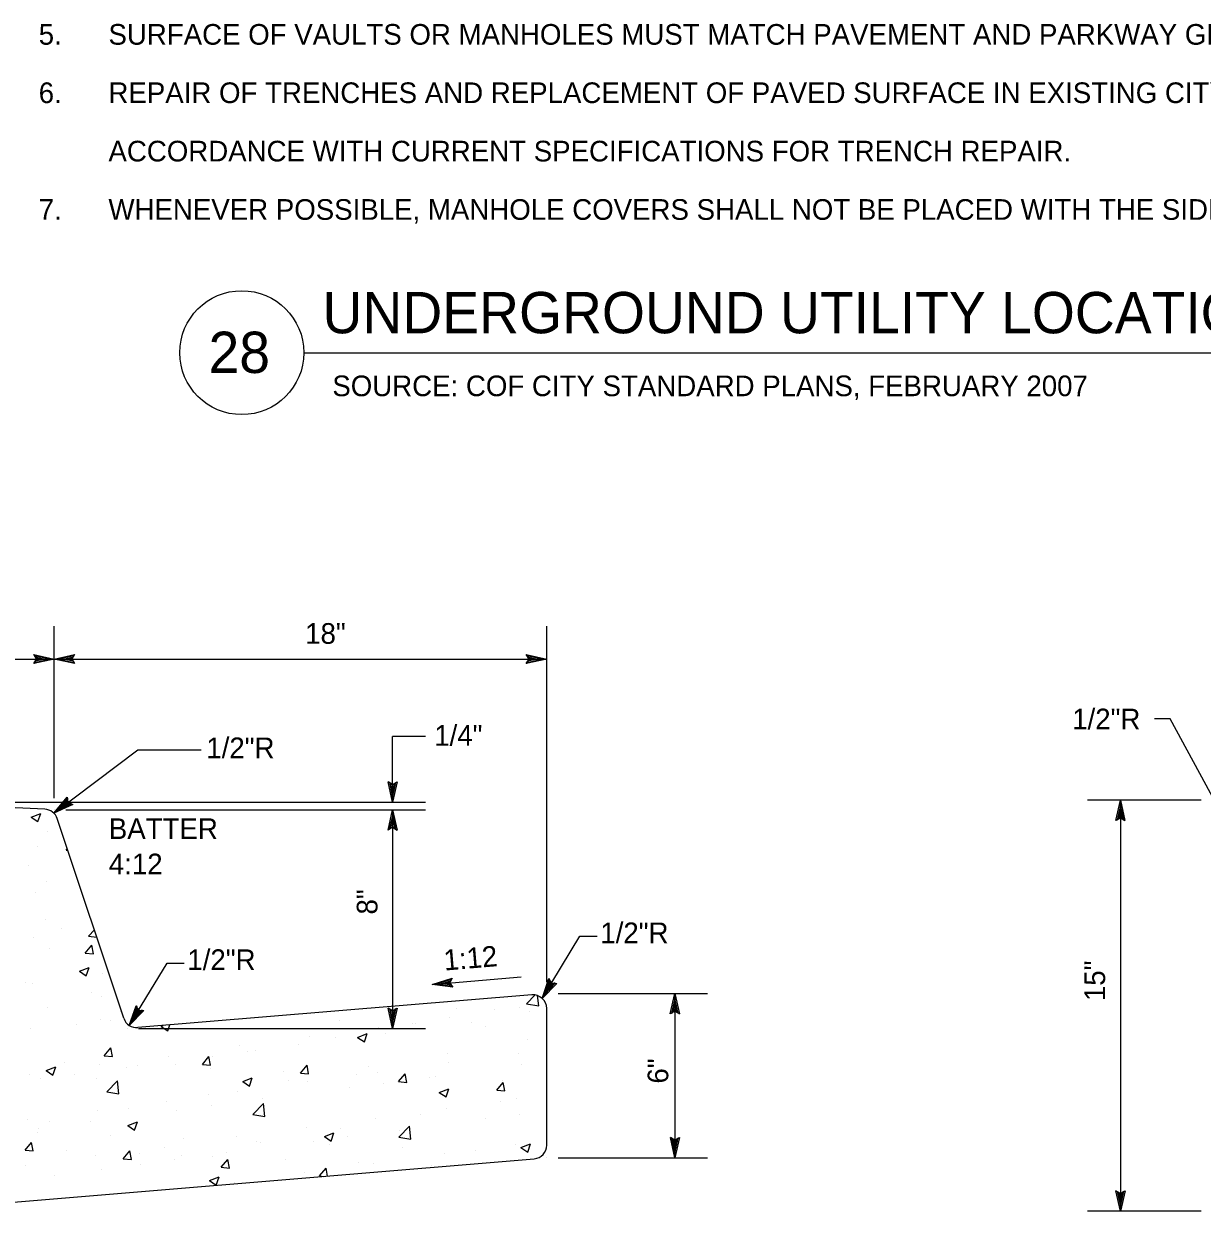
# Model space of a CAD drawing. Extents: x -119017 to -116080, y -104449 to -102845.
# Drawn here: x -118790 to -118447.9, y -103983.3 to -103638.4 of the extents above; entities that cross this region are included whole.
import ezdxf

# ---------------------------------------------------------------- set-up
doc = ezdxf.new("R2010")
doc.units = 0
for name, color, linetype in [('G-MARK', 7, 'Continuous'), ('G-TEXT', 7, 'Continuous'), ('Misc CnstDet(22)', 7, 'Continuous'), ('Nongeo Data(60)', 7, 'Continuous')]:
    doc.layers.add(name, color=color, linetype=linetype)

msp = doc.modelspace()

# ---------------------------------------------------------------- linework, layer by layer
at = {"layer": 'G-MARK'}
for p, q in [((-118781.19, -103863.3), (-118781.19, -103813.36)), ((-118638.22, -103916.71), (-118638.22, -103813.36)), ((-118828.88, -103822.9), (-118781.19, -103822.9)), ((-118781.19, -103822.9), (-118638.22, -103822.9)), ((-118682.94, -103864.49), (-118682.94, -103845.42)), ((-118673.4, -103845.42), (-118682.94, -103845.42)), ((-118448.18, -103863.93), (-118481.17, -103863.93)), ((-118471.63, -103863.93), (-118471.63, -103983.26)), ((-118825.53, -103864.49), (-118673.4, -103864.49)), ((-118777.85, -103866.65), (-118673.4, -103866.65)), ((-118682.94, -103866.65), (-118682.94, -103885.72)), ((-118682.94, -103876.19), (-118682.94, -103930.19)), ((-118671.49, -103917.37), (-118645.63, -103915.21)), ((-118634.87, -103920.06), (-118591.5, -103920.06)), ((-118601.01, -103920.06), (-118601.01, -103967.72)), ((-118756.68, -103930.19), (-118673.4, -103930.19)), ((-118634.87, -103967.72), (-118591.5, -103967.72)), ((-118448.18, -103983.26), (-118481.17, -103983.26))]:
    msp.add_line(p, q, dxfattribs=at)
for points in [[(-118443.61, -103865.21), (-118457.25, -103840.22), (-118461.72, -103840.22)], [(-118781.32, -103867.65), (-118756.89, -103849.23), (-118738.54, -103849.23)], [(-118639.5, -103921.44), (-118628.56, -103903.33), (-118623.59, -103903.33)]]:
    msp.add_lwpolyline(points, dxfattribs=at)
at = {"layer": 'G-TEXT'}
for points in [[(-118787.1, -103821.58), (-118781.19, -103822.9), (-118787.1, -103824.21), (-118786.89, -103823.86), (-118782.56, -103822.9), (-118786.89, -103821.93), (-118786.68, -103822.28), (-118783.91, -103822.9), (-118786.68, -103823.51), (-118786.47, -103823.16), (-118785.27, -103822.9), (-118786.47, -103822.63), (-118786.31, -103822.9), (-118787.1, -103824.21), (-118786.31, -103822.9)], [(-118775.29, -103824.22), (-118781.19, -103822.9), (-118775.29, -103821.59), (-118775.5, -103821.94), (-118779.82, -103822.9), (-118775.5, -103823.87), (-118775.7, -103823.52), (-118778.47, -103822.9), (-118775.71, -103822.29), (-118775.92, -103822.64), (-118777.11, -103822.9), (-118775.91, -103823.17), (-118776.07, -103822.9), (-118775.29, -103821.59), (-118776.07, -103822.9)], [(-118644.13, -103821.58), (-118638.22, -103822.9), (-118644.13, -103824.21), (-118643.92, -103823.86), (-118639.59, -103822.9), (-118643.92, -103821.93), (-118643.71, -103822.28), (-118640.94, -103822.9), (-118643.71, -103823.51), (-118643.5, -103823.16), (-118642.3, -103822.9), (-118643.5, -103822.63), (-118643.34, -103822.9), (-118644.13, -103824.21), (-118643.34, -103822.9)], [(-118681.62, -103858.59), (-118682.94, -103864.49), (-118684.25, -103858.59), (-118683.9, -103858.8), (-118682.94, -103863.12), (-118681.97, -103858.79), (-118682.32, -103859), (-118682.94, -103861.77), (-118683.55, -103859.01), (-118683.2, -103859.22), (-118682.93, -103860.41), (-118682.67, -103859.21), (-118682.94, -103859.37), (-118684.25, -103858.59), (-118682.94, -103859.37)], [(-118775.82, -103865.12), (-118781.32, -103867.65), (-118777.41, -103863.03), (-118777.37, -103863.43), (-118780.23, -103866.82), (-118776.2, -103864.97), (-118776.58, -103864.82), (-118779.15, -103866), (-118777.32, -103863.84), (-118777.28, -103864.24), (-118778.07, -103865.18), (-118776.95, -103864.66), (-118777.25, -103864.55), (-118777.41, -103863.03), (-118777.25, -103864.55)], [(-118472.95, -103869.83), (-118471.63, -103863.93), (-118470.32, -103869.83), (-118470.67, -103869.62), (-118471.63, -103865.3), (-118472.6, -103869.63), (-118472.25, -103869.42), (-118471.63, -103866.65), (-118471.02, -103869.41), (-118471.37, -103869.2), (-118471.64, -103868.01), (-118471.9, -103869.21), (-118471.63, -103869.05), (-118470.32, -103869.83), (-118471.63, -103869.05)], [(-118684.26, -103872.55), (-118682.94, -103866.65), (-118681.63, -103872.55), (-118681.98, -103872.34), (-118682.93, -103868.02), (-118683.91, -103872.35), (-118683.56, -103872.14), (-118682.94, -103869.37), (-118682.33, -103872.13), (-118682.68, -103871.92), (-118682.94, -103870.73), (-118683.21, -103871.93), (-118682.94, -103871.77), (-118681.63, -103872.55), (-118682.94, -103871.77)], [(-118665.5, -103918.23), (-118671.49, -103917.37), (-118665.71, -103915.61), (-118665.89, -103915.97), (-118670.13, -103917.26), (-118665.74, -103917.9), (-118665.97, -103917.56), (-118668.78, -103917.16), (-118666.07, -103916.34), (-118666.25, -103916.7), (-118667.43, -103917.06), (-118666.21, -103917.23), (-118666.39, -103916.97), (-118665.71, -103915.61), (-118666.39, -103916.97)], [(-118635.31, -103917.08), (-118639.5, -103921.44), (-118637.55, -103915.71), (-118637.36, -103916.07), (-118638.79, -103920.26), (-118635.71, -103917.07), (-118636.12, -103917.07), (-118638.09, -103919.11), (-118637.17, -103916.43), (-118636.98, -103916.79), (-118637.38, -103917.95), (-118636.53, -103917.07), (-118636.84, -103917.06), (-118637.55, -103915.71), (-118636.84, -103917.06)], [(-118602.33, -103925.97), (-118601.01, -103920.06), (-118599.7, -103925.97), (-118600.05, -103925.76), (-118601, -103921.43), (-118601.98, -103925.76), (-118601.63, -103925.55), (-118601.01, -103922.78), (-118600.4, -103925.55), (-118600.75, -103925.34), (-118601.01, -103924.14), (-118601.28, -103925.34), (-118601.01, -103925.18), (-118599.7, -103925.97), (-118601.01, -103925.18)], [(-118755.16, -103924.96), (-118759.4, -103929.29), (-118757.4, -103923.58), (-118757.21, -103923.94), (-118758.68, -103928.12), (-118755.57, -103924.95), (-118755.98, -103924.95), (-118757.96, -103926.98), (-118757.02, -103924.3), (-118756.84, -103924.66), (-118757.24, -103925.82), (-118756.38, -103924.94), (-118756.7, -103924.94), (-118757.4, -103923.58), (-118756.7, -103924.94)], [(-118681.62, -103924.29), (-118682.94, -103930.19), (-118684.25, -103924.29), (-118683.9, -103924.5), (-118682.94, -103928.82), (-118681.97, -103924.5), (-118682.32, -103924.7), (-118682.94, -103927.47), (-118683.55, -103924.71), (-118683.2, -103924.92), (-118682.93, -103926.11), (-118682.67, -103924.91), (-118682.94, -103925.07), (-118684.25, -103924.29), (-118682.94, -103925.07)], [(-118599.69, -103961.81), (-118601.01, -103967.72), (-118602.32, -103961.81), (-118601.97, -103962.02), (-118601.01, -103966.35), (-118600.04, -103962.02), (-118600.39, -103962.23), (-118601.01, -103965), (-118601.62, -103962.23), (-118601.27, -103962.44), (-118601, -103963.64), (-118600.74, -103962.44), (-118601.01, -103962.6), (-118602.32, -103961.81), (-118601.01, -103962.6)], [(-118470.31, -103977.35), (-118471.63, -103983.26), (-118472.94, -103977.35), (-118472.59, -103977.56), (-118471.64, -103981.89), (-118470.66, -103977.56), (-118471.01, -103977.77), (-118471.63, -103980.54), (-118472.24, -103977.77), (-118471.89, -103977.98), (-118471.63, -103979.18), (-118471.36, -103977.98), (-118471.63, -103978.14), (-118472.94, -103977.35), (-118471.63, -103978.14)]]:
    msp.add_lwpolyline(points, close=True, dxfattribs=at)
at = {"layer": 'Misc CnstDet(22)'}
for p, q in [((-118781.19, -103863.3), (-118781.19, -103813.36)), ((-118781.19, -103822.9), (-118781.19, -103822.9)), ((-118638.22, -103822.9), (-118638.22, -103822.9)), ((-118781.19, -103866.65), (-118781.19, -103866.65)), ((-118781.19, -103866.65), (-118781.19, -103866.65)), ((-118781.19, -103866.65), (-118781.19, -103866.65)), ((-118781.19, -103866.65), (-118781.19, -103866.65)), ((-118777.85, -103866.65), (-118673.4, -103866.65)), ((-118682.94, -103866.65), (-118682.94, -103866.65)), ((-118682.94, -103866.65), (-118682.94, -103866.65)), ((-118787.92, -103868.78), (-118785.13, -103867.71)), ((-118787.92, -103868.78), (-118785.95, -103870.12)), ((-118785.95, -103870.12), (-118785.13, -103867.71)), ((-118783.07, -103873.12), (-118783.07, -103873.12)), ((-118786.1, -103877.44), (-118786.1, -103877.44)), ((-118777.72, -103878.41), (-118777.41, -103878.03)), ((-118777.72, -103878.41), (-118777.25, -103878.44)), ((-118788.73, -103882.85), (-118788.73, -103882.85)), ((-118783.57, -103887.48), (-118783.57, -103887.48)), ((-118786.57, -103890.63), (-118786.57, -103890.63)), ((-118783.82, -103898.58), (-118783.82, -103898.58)), ((-118778.97, -103901.14), (-118778.97, -103901.14)), ((-118771.22, -103903.33), (-118769.53, -103901.58)), ((-118787.07, -103903.86), (-118787.07, -103903.86)), ((-118771.22, -103903.33), (-118768.84, -103903.71)), ((-118782.57, -103906.99), (-118782.57, -103906.99)), ((-118772.19, -103908.27), (-118770.28, -103905.99)), ((-118772.19, -103908.27), (-118769.81, -103908.49)), ((-118769.81, -103908.49), (-118770.28, -103905.99)), ((-118773.87, -103913.56), (-118771.09, -103912.49)), ((-118773.87, -103913.56), (-118771.9, -103914.9)), ((-118771.9, -103914.9), (-118771.09, -103912.49)), ((-118767.15, -103914.27), (-118767.15, -103914.27)), ((-118789.42, -103916.81), (-118789.42, -103916.81)), ((-118787.54, -103917.09), (-118787.54, -103917.09)), ((-118770.34, -103919.78), (-118770.34, -103919.78)), ((-118767.4, -103920.87), (-118767.4, -103920.87)), ((-118644.07, -103923.06), (-118641.53, -103920.44)), ((-118640.53, -103923.63), (-118640.88, -103920.62)), ((-118638.22, -103920.06), (-118638.22, -103920.06)), ((-118638.22, -103920.06), (-118638.22, -103920.06)), ((-118783.16, -103924.22), (-118783.16, -103924.22)), ((-118761.96, -103925.13), (-118761.96, -103925.13)), ((-118664.33, -103924.25), (-118664.33, -103924.25)), ((-118653.26, -103924.69), (-118653.26, -103924.69)), ((-118645.98, -103924.09), (-118645.98, -103924.09)), ((-118644.07, -103923.06), (-118640.53, -103923.63)), ((-118643.16, -103925.16), (-118643.16, -103925.16)), ((-118774.78, -103929.16), (-118774.78, -103929.16)), ((-118767.65, -103927.5), (-118767.65, -103927.5)), ((-118764.84, -103927.88), (-118764.84, -103927.88)), ((-118750.17, -103929.57), (-118749.55, -103929.32)), ((-118750.17, -103929.57), (-118748.2, -103930.88)), ((-118748.2, -103930.88), (-118747.61, -103929.16)), ((-118719.59, -103926.91), (-118719.59, -103926.91)), ((-118698.39, -103927.82), (-118698.39, -103927.82)), ((-118677.18, -103928.69), (-118677.18, -103928.69)), ((-118676.4, -103928.66), (-118676.4, -103928.66)), ((-118666.36, -103926.91), (-118666.36, -103926.91)), ((-118660.11, -103928.38), (-118660.11, -103928.38)), ((-118655.98, -103929.6), (-118655.98, -103929.6)), ((-118788.04, -103930.32), (-118788.04, -103930.32)), ((-118759.99, -103930.19), (-118759.99, -103930.19)), ((-118707.05, -103932.41), (-118707.05, -103932.41)), ((-118699.57, -103932.66), (-118699.57, -103932.66)), ((-118693.1, -103932.76), (-118690.32, -103931.66)), ((-118693.1, -103932.76), (-118691.13, -103934.07)), ((-118691.13, -103934.07), (-118690.32, -103931.66)), ((-118687, -103929.88), (-118687, -103929.88)), ((-118685.1, -103931.66), (-118685.1, -103931.66)), ((-118682.94, -103930.19), (-118682.94, -103930.19)), ((-118675.15, -103930.35), (-118675.15, -103930.35)), ((-118766.68, -103938.13), (-118764.77, -103935.85)), ((-118764.31, -103938.35), (-118764.77, -103935.85)), ((-118727.44, -103935.23), (-118727.44, -103935.23)), ((-118710.18, -103934.95), (-118710.18, -103934.95)), ((-118643.72, -103933.41), (-118643.72, -103933.41)), ((-118766.68, -103938.13), (-118764.31, -103938.35)), ((-118748.08, -103938.2), (-118748.08, -103938.2)), ((-118738.19, -103940.64), (-118736.29, -103938.35)), ((-118735.82, -103940.86), (-118736.29, -103938.35)), ((-118735.16, -103938.26), (-118735.16, -103938.26)), ((-118725.22, -103936.95), (-118725.22, -103936.95)), ((-118722.72, -103936.63), (-118722.72, -103936.63)), ((-118666.9, -103937.38), (-118666.9, -103937.38)), ((-118646.44, -103937.32), (-118646.44, -103937.32)), ((-118783.54, -103942.36), (-118780.75, -103941.29)), ((-118783.54, -103942.36), (-118781.57, -103943.7)), ((-118781.57, -103943.7), (-118780.75, -103941.29)), ((-118778.25, -103939.98), (-118778.25, -103939.98)), ((-118768.12, -103940.73), (-118768.12, -103940.73)), ((-118760.24, -103941.54), (-118760.24, -103941.54)), ((-118757.05, -103940.86), (-118757.05, -103940.86)), ((-118745.89, -103940.61), (-118745.89, -103940.61)), ((-118738.19, -103940.64), (-118735.82, -103940.86)), ((-118735.85, -103941.76), (-118735.85, -103941.76)), ((-118714.65, -103942.64), (-118714.65, -103942.64)), ((-118709.71, -103943.14), (-118707.8, -103940.86)), ((-118709.71, -103943.14), (-118707.33, -103943.33)), ((-118707.33, -103943.33), (-118707.8, -103940.86)), ((-118690.07, -103941.36), (-118690.07, -103941.36)), ((-118687.47, -103943.11), (-118687.47, -103943.11)), ((-118681.22, -103945.61), (-118679.31, -103943.36)), ((-118678.84, -103945.83), (-118679.31, -103943.36)), ((-118666.83, -103940.1), (-118666.83, -103940.1)), ((-118645.48, -103940.73), (-118645.48, -103940.73)), ((-118788.51, -103943.51), (-118788.51, -103943.51)), ((-118785.23, -103944.83), (-118785.23, -103944.83)), ((-118775.28, -103943.54), (-118775.28, -103943.54)), ((-118769.06, -103944.58), (-118769.06, -103944.58)), ((-118765.96, -103948.61), (-118762.87, -103945.39)), ((-118762.43, -103949.14), (-118762.87, -103945.39)), ((-118726.47, -103945.55), (-118723.68, -103944.48)), ((-118726.47, -103945.55), (-118724.5, -103946.89)), ((-118724.5, -103946.89), (-118723.68, -103944.48)), ((-118713.21, -103945.36), (-118713.21, -103945.36)), ((-118707.52, -103945.64), (-118707.52, -103945.64)), ((-118693.45, -103943.54), (-118693.45, -103943.54)), ((-118685.6, -103946.02), (-118685.6, -103946.02)), ((-118681.22, -103945.61), (-118678.84, -103945.83)), ((-118672.24, -103944.45), (-118672.24, -103944.45)), ((-118670.55, -103944.05), (-118670.55, -103944.05)), ((-118652.73, -103948.11), (-118650.82, -103945.83)), ((-118651.04, -103945.33), (-118651.04, -103945.33)), ((-118650.35, -103948.33), (-118650.82, -103945.83)), ((-118765.96, -103948.61), (-118762.43, -103949.14)), ((-118736.38, -103949.33), (-118736.38, -103949.33)), ((-118727.94, -103948.42), (-118727.94, -103948.42)), ((-118695.54, -103947.33), (-118695.54, -103947.33)), ((-118669.4, -103948.74), (-118666.61, -103947.67)), ((-118669.4, -103948.74), (-118667.43, -103950.05)), ((-118667.43, -103950.05), (-118666.61, -103947.67)), ((-118652.73, -103948.11), (-118650.35, -103948.33)), ((-118759.52, -103953.3), (-118759.52, -103953.3)), ((-118748.55, -103951.43), (-118748.55, -103951.43)), ((-118735.66, -103952.61), (-118735.66, -103952.61)), ((-118723.56, -103955.18), (-118720.46, -103951.96)), ((-118720.62, -103950.61), (-118720.62, -103950.61)), ((-118720.03, -103955.74), (-118720.46, -103951.96)), ((-118667.33, -103953.33), (-118667.33, -103953.33)), ((-118651.73, -103951.3), (-118651.73, -103951.3)), ((-118646.94, -103950.55), (-118646.94, -103950.55)), ((-118789.01, -103956.74), (-118789.01, -103956.74)), ((-118768.62, -103953.96), (-118768.62, -103953.96)), ((-118745.61, -103953.9), (-118745.61, -103953.9)), ((-118723.56, -103955.18), (-118720.03, -103955.74)), ((-118687.94, -103956.3), (-118687.94, -103956.3)), ((-118674.87, -103955.27), (-118674.87, -103955.27)), ((-118655.92, -103956.4), (-118655.92, -103956.4)), ((-118646.01, -103955.08), (-118646.01, -103955.08)), ((-118785.98, -103960.27), (-118785.98, -103960.27)), ((-118785.73, -103959.18), (-118785.73, -103959.18)), ((-118782.69, -103957.27), (-118782.69, -103957.27)), ((-118770.69, -103957.21), (-118770.69, -103957.21)), ((-118759.83, -103958.37), (-118757.05, -103957.3)), ((-118759.83, -103958.37), (-118757.86, -103959.68)), ((-118757.86, -103959.68), (-118757.05, -103957.3)), ((-118708.02, -103958.87), (-118708.02, -103958.87)), ((-118702.76, -103961.53), (-118699.98, -103960.46)), ((-118700.79, -103962.87), (-118699.98, -103960.46)), ((-118698.04, -103959.24), (-118698.04, -103959.24)), ((-118681.19, -103961.74), (-118678.09, -103958.52)), ((-118681.03, -103959.68), (-118681.03, -103959.68)), ((-118677.65, -103962.31), (-118678.09, -103958.52)), ((-118789.67, -103965.53), (-118787.76, -103963.25)), ((-118787.29, -103965.75), (-118787.76, -103963.25)), ((-118764.77, -103961.15), (-118764.77, -103961.15)), ((-118743.57, -103962.06), (-118743.57, -103962.06)), ((-118728.41, -103961.65), (-118728.41, -103961.65)), ((-118722.37, -103962.93), (-118722.37, -103962.93)), ((-118721.21, -103963.21), (-118721.21, -103963.21)), ((-118705.98, -103963), (-118705.98, -103963)), ((-118702.76, -103961.53), (-118700.79, -103962.87)), ((-118701.17, -103963.84), (-118701.17, -103963.84)), ((-118696.07, -103961.68), (-118696.07, -103961.68)), ((-118681.19, -103961.74), (-118677.65, -103962.31)), ((-118647.41, -103963.75), (-118647.41, -103963.75)), ((-118645.69, -103964.72), (-118642.91, -103963.65)), ((-118643.72, -103966.06), (-118642.91, -103963.65)), ((-118789.67, -103965.53), (-118787.29, -103965.75)), ((-118777.6, -103965.59), (-118777.6, -103965.59)), ((-118769.09, -103967.19), (-118769.09, -103967.19)), ((-118761.18, -103968.03), (-118759.27, -103965.75)), ((-118758.8, -103968.22), (-118759.27, -103965.75)), ((-118756.39, -103966.5), (-118756.39, -103966.5)), ((-118749.05, -103964.62), (-118749.05, -103964.62)), ((-118744.35, -103967.19), (-118744.35, -103967.19)), ((-118735.22, -103967.37), (-118735.22, -103967.37)), ((-118731.1, -103966.28), (-118731.1, -103966.28)), ((-118679.97, -103964.75), (-118679.97, -103964.75)), ((-118667.8, -103966.56), (-118667.8, -103966.56)), ((-118658.77, -103965.62), (-118658.77, -103965.62)), ((-118645.69, -103964.72), (-118643.72, -103966.06)), ((-118789.48, -103969.97), (-118789.48, -103969.97)), ((-118761.18, -103968.03), (-118758.8, -103968.22)), ((-118756.05, -103969.56), (-118756.05, -103969.56)), ((-118746.14, -103968.28), (-118746.14, -103968.28)), ((-118732.69, -103970.5), (-118730.78, -103968.22)), ((-118732.69, -103970.5), (-118730.31, -103970.72)), ((-118730.31, -103970.72), (-118730.78, -103968.22)), ((-118714.02, -103968.28), (-118714.02, -103968.28)), ((-118704.2, -103973), (-118702.29, -103970.72)), ((-118701.86, -103973.03), (-118702.29, -103970.72)), ((-118692.82, -103969.19), (-118692.82, -103969.19)), ((-118688.44, -103969.53), (-118688.44, -103969.53)), ((-118671.62, -103970.06), (-118671.62, -103970.06)), ((-118638.22, -103967.72), (-118638.22, -103967.72)), ((-118601.01, -103967.72), (-118601.01, -103967.72)), ((-118781.16, -103972.88), (-118781.16, -103972.88)), ((-118767.53, -103971.16), (-118767.53, -103971.16)), ((-118736.13, -103974.35), (-118733.35, -103973.28)), ((-118736.13, -103974.35), (-118734.16, -103975.69)), ((-118734.16, -103975.69), (-118733.35, -103973.28)), ((-118708.49, -103972.06), (-118708.49, -103972.06)), ((-118704.2, -103973), (-118702.98, -103973.13)), ((-118728.88, -103974.88), (-118728.88, -103974.88)), ((-118471.63, -103983.26), (-118471.63, -103983.26))]:
    msp.add_line(p, q, dxfattribs=at)
for points in [[(-118783.91, -103866.52), (-118824.72, -103864.68)], [(-118760.99, -103927.22), (-118780.32, -103869.24)], [(-118759.4, -103929.29), (-118748.45, -103911.18), (-118743.51, -103911.18)], [(-118642.5, -103920.4), (-118756.89, -103929.94)], [(-118638.22, -103964.06), (-118638.22, -103924.38)], [(-118824.57, -103983.26), (-118641.85, -103968)]]:
    msp.add_lwpolyline(points, dxfattribs=at)
for centre, start, end in [((-118784.09, -103870.5), 18.435, 87.3974), ((-118642.19, -103924.36), 0, 94.7636), ((-118757.22, -103925.98), 198.435, 274.7636), ((-118642.19, -103964.05), 274.7742, 0)]:
    msp.add_arc(centre, 3.97, start, end, dxfattribs=at)
at = {"layer": 'Nongeo Data(60)'}
msp.add_line((-118708.74, -103733.93), (-118332.37, -103733.93), dxfattribs=at)
msp.add_circle((-118726.74, -103733.93), 18, dxfattribs=at)

# ---------------------------------------------------------------- texts
at = {"layer": 'Misc CnstDet(22)'}
for s, height, p in [('5.', 6, (-118785.7, -103644.5)), ('SURFACE OF VAULTS OR MANHOLES MUST MATCH PAVEMENT AND PARKWAY GRADES.', 6, (-118765.45, -103644.5)), ('6.', 6, (-118785.7, -103661.45)), ('REPAIR OF TRENCHES AND REPLACEMENT OF PAVED SURFACE IN EXISTING CITY ROADS SHALL BE IN', 6, (-118765.45, -103661.45)), ('ACCORDANCE WITH CURRENT SPECIFICATIONS FOR TRENCH REPAIR.', 6, (-118765.45, -103678.4)), ('7.', 6, (-118785.7, -103695.35)), ('WHENEVER POSSIBLE, MANHOLE COVERS SHALL NOT BE PLACED WITH THE SIDEWALKS.', 6, (-118765.45, -103695.35)), ('UNDERGROUND UTILITY LOCATION', 12, (-118703.31, -103728.3)), ('28', 12, (-118736.39, -103739.83)), ('SOURCE: COF CITY STANDARD PLANS, FEBRUARY 2007', 6, (-118700.45, -103746.57)), ('18"', 6, (-118708.34, -103818.47)), ('1/2"R', 6, (-118485.65, -103843.31)), ('1/2"R', 6, (-118737.04, -103851.69)), ('BATTER', 6, (-118765.34, -103875.15)), ('4:12', 6, (-118765.34, -103885.41)), ('1/2"R', 6, (-118622.65, -103905.41)), ('1/2"R', 6, (-118742.54, -103913.21))]:
    msp.add_text(s, height=height, dxfattribs=at).set_placement(p)
for s, rotation, p in [('1/4"', 0.001, (-118670.87, -103848.08)), ('8"', 90, (-118687.36, -103897.08)), ('1:12', 4.7636, (-118667.88, -103913.37)), ('15"', 90, (-118476.09, -103922.23)), ('6"', 90, (-118602.92, -103946.19))]:
    msp.add_text(s, height=6, rotation=rotation, dxfattribs=at).set_placement(p)

doc.saveas('drawing.dxf')
